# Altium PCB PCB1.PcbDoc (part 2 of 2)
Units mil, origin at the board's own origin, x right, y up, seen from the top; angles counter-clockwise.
Board outline 2130 x 2330 mil, 2 copper layers (Top Layer, Bottom Layer); 110 components, 79 nets, 324 pads, 362 vias.
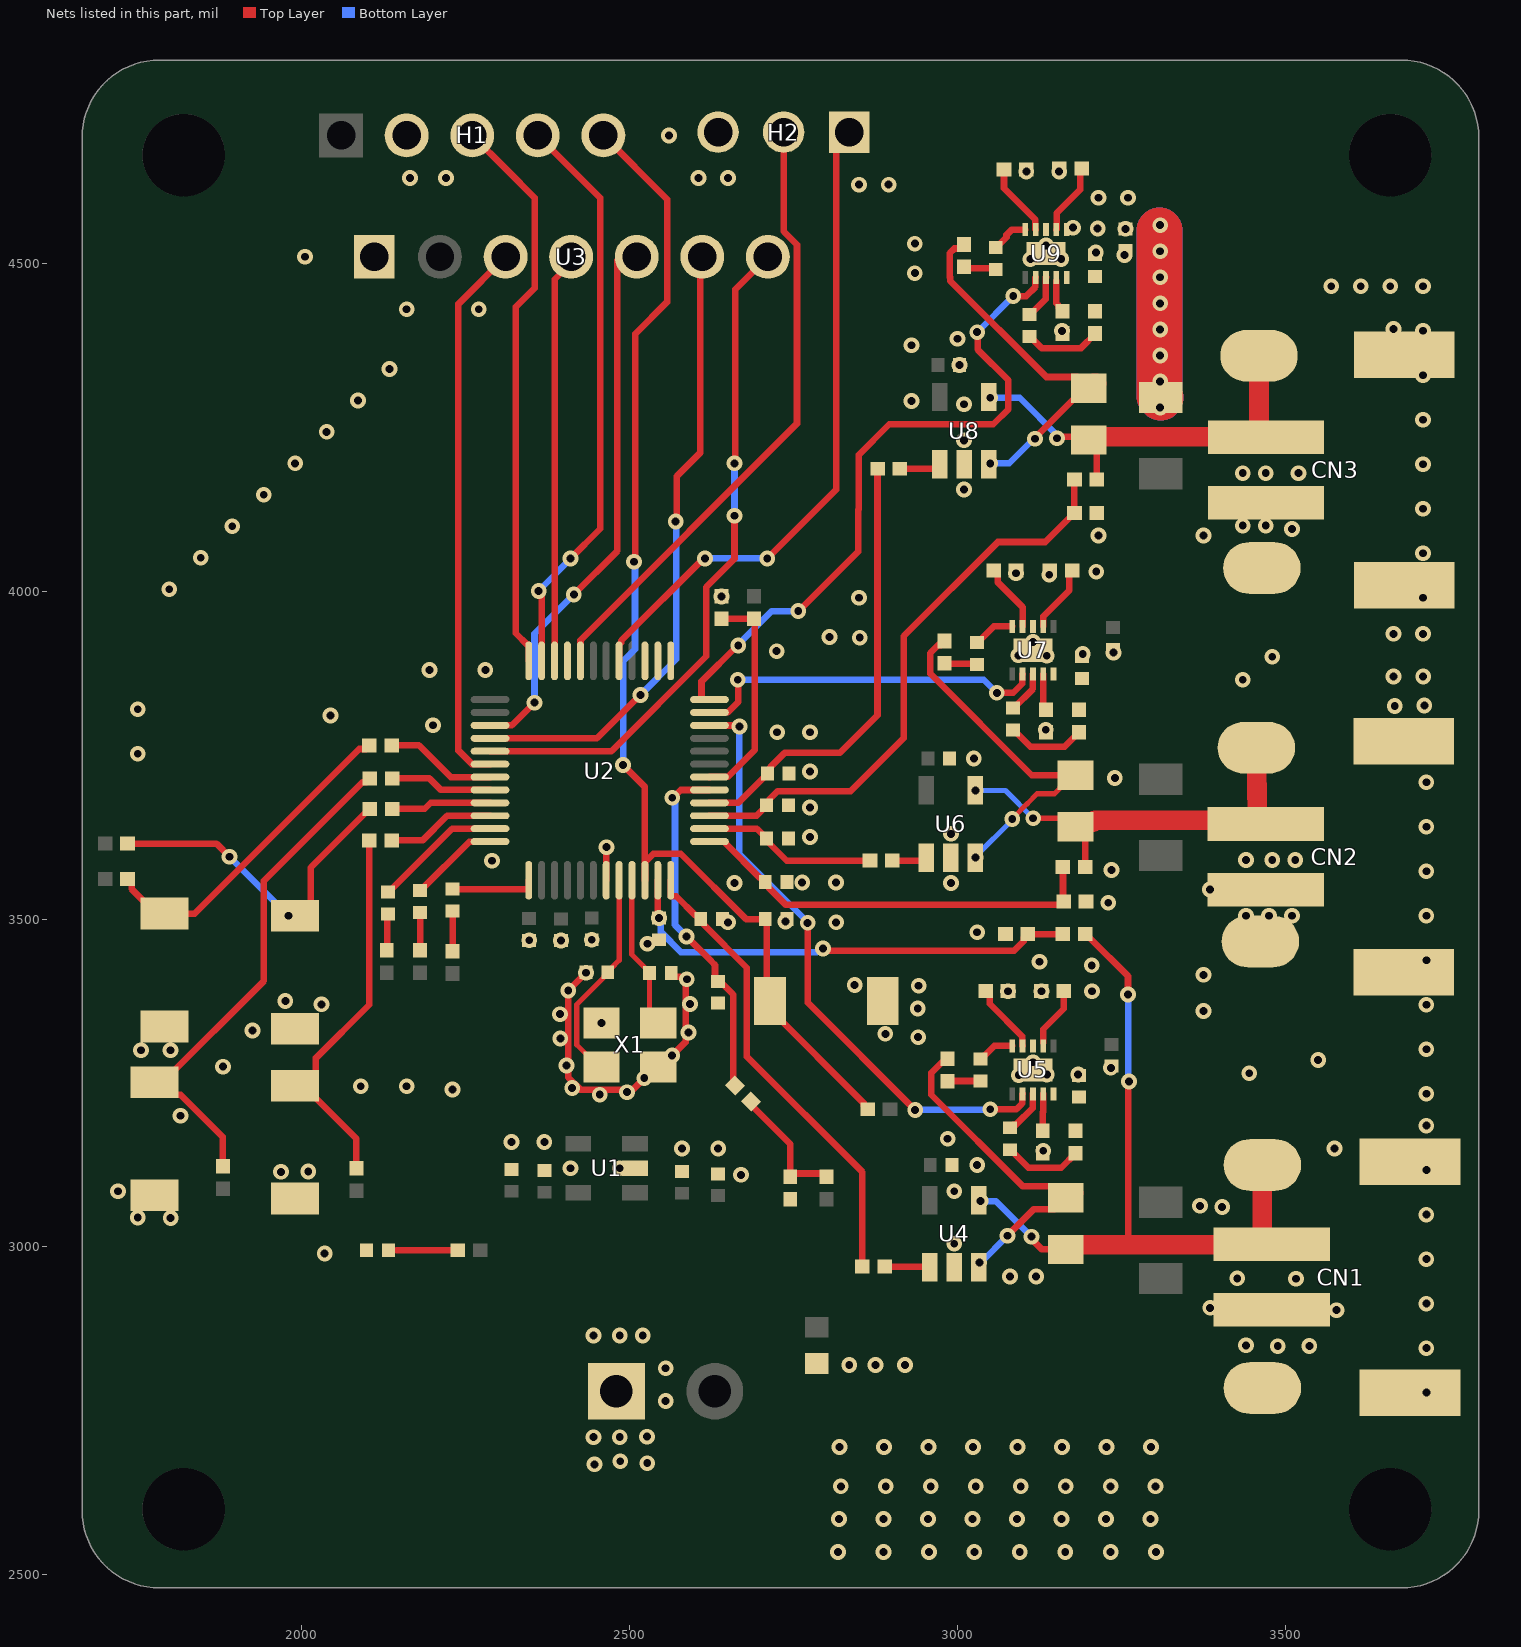
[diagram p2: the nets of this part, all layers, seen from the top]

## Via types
v1: diameter 24, hole 12, Top Layer to Bottom Layer, tented both sides, 362 vias

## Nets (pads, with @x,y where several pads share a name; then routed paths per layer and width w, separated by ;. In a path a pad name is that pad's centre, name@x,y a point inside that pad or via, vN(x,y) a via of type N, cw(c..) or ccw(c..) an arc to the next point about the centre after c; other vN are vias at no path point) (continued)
5V_3: C25.2 R41.1 U9.1 | length 510.5
  Top Layer w70: v1@3308.28,4550.18 3308.28,4513.15 3308.28,4438.95 3308.28,4399.21 3308.28,4359.47 3308.28,4297.34 R41.1@3310,4295.62
  Bottom Layer w70: v1@3308.28,4550.18 3308.28,4513.15 3308.28,4297.34 3310,4295.62
  other v1: 3309.09,4280 3309.09,4319.74 3309.09,4359.47 3309.09,4399.21 3309.09,4438.95 3309.09,4478.69 3309.09,4518.42 3213.76,4553.23 3256.34,4552.54 3176.23,4554.41 3309.09,4558.16 3215,4600 3260,4600
ADC1_IN0: C14.1 R8.2 R13.1 U2.11 | length 723.5
  Top Layer w10: U2.11@2543.08,3559.14 2543.07,3503.47 v1(2545,3501.54) ; v1(2795,3455) 2798.79,3455 2802.03,3451.76 3086.38,3451.76 3101.22,3466.61 3101.22,3471.52 3106.85,3477.15 R8.2@3160.51,3477.15
  Bottom Layer w10: v1(2545,3501.54) 2547.68,3498.86 2547.68,3480.15 2578.39,3449.45 2785.66,3449.45 2791.21,3455 v1(2795,3455)
ADC1_IN1: C15.1 R9.2 U2.12 | length 716.1
  Top Layer w10: U2.12@2562.77,3559.14 2562.77,3535.1 2563.06,3534.81 2571.23,3534.81 2600.41,3505.63 2603.62,3505.63 2608.46,3500.79 C15.1@2608.46,3500 ; C15.1@2608.46,3499.21 2613.3,3494.37 2613.3,3491.29 2678.77,3425.82 2678.77,3290.38 2855,3114.15 R9.2@2855,2970
ADC1_IN2: C21.1 R32.2 R34.1 U2.13 | length 637.8
  Top Layer w10: U2.13@2621.82,3618.19 2645.86,3618.19 2646.15,3617.9 2646.15,3615.56 2699.75,3561.96 2701.98,3561.96 2706.82,3557.12 C21.1@2706.82,3556.33 2711.66,3551.49 2711.66,3548.32 2738.35,3521.63 3156.69,3521.63 R34.1@3161.89,3526.83 ; R34.1@3160.93,3526.83 R32.2@3160.93,3578.69
ADC1_IN3: C22.1 R33.2 U2.14 | length 266.9
  Top Layer w10: U2.14@2621.82,3637.88 2694.09,3637.88 2703.52,3628.45 2704.11,3628.45 2708.95,3623.61 C22.1@2708.95,3623.02 ; C22.1@2708.95,3622.82 2713.79,3617.98 2713.79,3615.03 2739.71,3589.12 R33.2@2866.55,3589.12
ADC1_IN4: C24.1 R40.2 R44.1 U2.15 | length 893.4
  Top Layer w10: U2.15@2621.82,3657.56 2693.67,3657.56 2708.95,3672.84 2708.95,3674.42 2713.79,3679.26 2713.79,3683.1 2725.95,3695.26 2837.37,3695.26 2918.07,3775.96 2918.07,3931.48 3061.59,4075 3133.85,4075 3177.87,4119.02 R44.1@3178.37,4119.02 R40.2@3178.37,4170.41
ADC1_IN5: C27.1 R43.2 U2.16 | length 690.6
  Top Layer w10: U2.16@2621.82,3677.25 2621.94,3677.37 2665.96,3677.37 2710.04,3721.44 2710.04,3723.02 2714.88,3727.86 2714.88,3731.85 2736.42,3753.38 2820.6,3753.38 2878.03,3810.82 R43.2@2878.03,4186.63
ADC1_IN6: C12.2 R4.2 U2.17 | length 542.1
  Top Layer w10: v1(2565,3685) 2565.98,3685 2577.86,3696.88 U2.17@2621.82,3696.93 ; v1(2586.82,3473.54) 2625.2,3435.16 2625.2,3434.84 2630.2,3429.84 2630.2,3409.8 2639.84,3400.16 2642.79,3400.16 2658.03,3384.92 2658.03,3256.79 2660.47,3254.35 2660.47,3246.39 R4.2@2660.83,3246.03
  Bottom Layer w10: v1(2565,3685) 2565,3681.21 2569.25,3676.96 2569.25,3491.11 v1(2586.82,3473.54)
ADC1_IN7: R2.2 R5.2 U2.18 | length 336.7
  Top Layer w10: U2.18@2621.82,3716.62 2621.94,3716.74 2649.54,3716.74 2691.17,3758.37 2691.17,3956.79 R2.2@2690,3957.96 R5.2@2640,3957.96
GND: C1.2 C2.2 C3.1 C4.2 C5.2 C6.2 C7.2 C8.2 C9.2 C10.1 C11.1 C12.1 C13.1 C14.2 C15.2 C16.1 C17.1 C18.1 C19.1 C20.1 C21.2 C22.2 C23.1 C24.2 C25.1 C26.1 C27.2 CN1.2 CN1.3 CN1.4 CN2.2 CN2.3 CN2.4 CN3.2 CN3.3 CN3.4 H1.2 H2.3 LED2.1 P1.1 pad.2@3462,3465.84 pad.2@3464.28,4035.33 pad.2@3465,2785 R5.1 R6.1 R12.2 R13.2 R19.1 R20.1 R31.2 R34.2 R36.1 R37.1 R42.2 R44.2 R46.1 R48.1 SW1.1 SW2.1 SW3.1 SW4.1 SW5.1 U1.2 U2.7 U3.1 U4.2 U5.3 U5.11 U6.2 U7.3 U7.11 U8.2 U9.3 U9.11 X1.2 X1.4 | length 561.3
  Top Layer w10: C5.2@2433.58,3418.96 v1(2433.58,3418.17) v1(2406.49,3391.08) 2406.49,3258.52 2424.93,3240.08 2505.11,3240.08 2539.73,3274.7 X1.4@2543.67,3274.7 2547.6,3274.7 2585.45,3312.54 2585.45,3407.91 2581.66,3407.91 2577.46,3412.1 2568.32,3412.1 2563.48,3416.94 C10.1@2563.48,3417.73 ; U2.7@2464.34,3559.14 2464.34,3609.34 v1(2464.67,3609.67) v1@2465,3610
  other v1: 2817.86,2535 2887.14,2535 2956.43,2535 3025.71,2535 3095,2535 3164.29,2535 3233.57,2535 3302.86,2535 2819.29,2585 2887.14,2585 2955,2585 3022.86,2585 3090.71,2585 3158.57,2585 3226.43,2585 3294.29,2585 2822.14,2635 2890.71,2635 2959.29,2635 3027.86,2635 3096.43,2635 3165,2635 3233.57,2635 3302.14,2635 2446.52,2668.55 2526.89,2670.37 2485.79,2673.28 2820,2695 2887.86,2695 2955.71,2695 3023.57,2695 3091.43,2695 3159.29,2695 3227.14,2695 3295,2695 2445,2710 2485,2710 2526.53,2710.74 2555,2765 3715,2777.86 2555,2815 2835,2820 2875,2820 2920,2820 3715,2845.71 3488.43,2848.78 3536.61,2849.12 3440,2850 2445,2865 2485,2865 2520,2865 3578.06,2903.69 3385.32,2907.12 3715,2913.57 3426.65,2952.17 3516.09,2951.59 3080,2955 3120,2955 3715,2981.43 2035,2990 2995,3005 1800.18,3044.25 1750,3045 3715,3049.29 3403.64,3061.12 3369.68,3062.66 1720,3085 2995,3085 2670,3110 1968.49,3114.59 2010,3115 3715,3117.14 2410,3120 2485,3120 3030,3125 3130.83,3146.63 2580,3150 2635,3150 3575,3150 2320,3160 2370,3160 2985,3165 3715,3185 1815,3200 2454.56,3232.32 3715,3233.57 2496.02,3236.09 2230,3240 2412.37,3242.45 2090,3245 2160,3245 2522.42,3257.39 3093.47,3261.97 3136.31,3262.86 3183.97,3262.95 3445,3265 3233.86,3273.17 1880,3275 2403.68,3276.65 3115.19,3281.75 3550,3285 2564.91,3292.01 1755,3300 1800,3300 3715,3301.43 2394.45,3318.02 2940,3320 2890,3325 2589.68,3327.19 1925,3330 2457.05,3341.63 2393.87,3355 3375,3360 2939.42,3363.65 3715,3369.29 2030,3370 2592.05,3370.63 1975,3375 3077.04,3390 3127.96,3390 3205,3390 2940.82,3398.4 2843.24,3399.46 2587.3,3408.24 3375,3415 3204.71,3429.49 3125,3435 3715,3437.14 2527.37,3462.32 2395.45,3467.22 2346.91,3467.65 2442.28,3468.5 3030,3480 2650,3495 2815,3495 2737.58,3496.3 3440,3505 3475,3505 3510,3505 3715,3505 3230,3525 3385,3545 2660,3555 2990,3555 2763.12,3555.81 2814.63,3555.94 3715,3572.86 3235,3575 2290.28,3588.86 3440,3590 3480,3590 3515,3590 2775,3625 2990,3630 3715,3640.71 2775,3670 3715,3708.57 3240,3715 2775,3725 3025,3745 1750,3752.14 2725,3785 2775,3785 3134.63,3788.73 2200.07,3795.54 2043.73,3810.45 1750,3820 3666.89,3824.99 3711.99,3825.59 3435,3865 3665,3870 3710.16,3870.08 2195,3880 2280,3880 3480,3900 3093.18,3902.2 3136.07,3901.63 3191.07,3904.31 3237.99,3906.26 2724.25,3908.61 3115.12,3922.45 2851.01,3929.19 2805,3930 3665,3935 3710,3935 2850,3990 3710,3990 2640,3992.04 1798.07,4003.07 3140,4025 3089.06,4027.34 3211.66,4029.77 1846.05,4051.05 3710,4057.86 3215,4085 3375,4085 3510,4095 1894.04,4099.04 3435,4100 3470,4100 3710,4125.71 1942.02,4147.02 3010,4155 3435,4180 3470,4180 3520,4180 3710,4193.57 1990,4195 3010,4230 2037.98,4242.98 3710,4261.43 3010,4285 2930,4290 2085.96,4290.96 3710,4329.29 2133.95,4338.95 3003.08,4345 2930,4375 3000,4385 3159.41,4397.06 3710,4397.14 3665,4400 2160,4430 2270,4430 3570,4465 3615,4465 3660,4465 3710,4465 2935,4485 3111.11,4506.4 3158.15,4506.73 2005,4510 3254.86,4512.55 3210.96,4516.66 3135.05,4527.14 2935,4530 2850,4620 2895,4620 2165,4630 2220,4630 2605,4630 2650,4630 3105,4640 3155,4640 2560,4695
NetC5_1: C5.1 U2.8 X1.3 | length 329.3
  Top Layer w8: X1.3@2457.05,3274.7 2453.11,3274.7 2419.49,3308.32 2419.49,3369.94 2460.81,3411.27 2460.81,3413.11 C5.1@2466.66,3418.96 2466.66,3419.74 2472.5,3425.59 2484.31,3437.39 2484.31,3558.86 U2.8@2484.03,3559.14
NetC10_2: C10.2 U2.9 X1.1 | length 234.4
  Top Layer w8: U2.9@2503.71,3559.14 2503.71,3546.1 2503.25,3545.65 2503.25,3446.08 2524.56,3424.77 2524.56,3423.57 C10.2@2530.4,3417.73 ; C10.2@2530.4,3417.73 2530.39,3354.9 X1.1@2543.67,3341.63
NetLED1_1: LED1.1 U5.5 | length 56.7
  Top Layer w10: LED1.1@3035,3286.73 3039.84,3291.57 3041.02,3291.57 3055.97,3306.52 U5.5@3083.5,3306.52
NetLED1_2: LED1.2 R7.1 | length 50.1
  Top Layer w10: R7.1@2985,3252.96 2985.16,3253.12 3034.85,3253.12 LED1.2@3035,3253.27
NetLED2_2: LED2.2 R11.1 | length 80.3
  Top Layer w10: 2145,2995 2225.34,2995
NetLED3_1: LED3.1 U5.8 | length 68.8
  Top Layer w10: LED3.1@3080,3181.73 3084.84,3186.57 3089.28,3186.57 3114.66,3211.95 3114.66,3233.14 U5.8@3115,3233.48
NetLED3_2: LED3.2 R16.1 | length 120.8
  Top Layer w10: LED3.2@3080,3148.27 3080.79,3148.27 3108.23,3120.83 3158.37,3120.83 3180,3142.46 R16.1@3180,3142.96
NetLED4_2: LED4.2 R18.1 | length 61.1
  Top Layer w10: R18.1@2230,3451.07 LED4.2@2230,3512.18
NetLED5_2: LED5.2 R23.1 | length 56.1
  Top Layer w10: R23.1@2129.65,3452.27 2130.67,3453.3 2130.67,3506.52 LED5.2@2131.7,3507.55
NetLED6_2: LED6.2 R25.1 | length 57.8
  Top Layer w10: R25.1@2180.51,3452.27 LED6.2@2180.51,3510.1
NetLED7_1: LED7.1 U7.5 | length 63.8
  Top Layer w10: LED7.1@3030,3921.73 3030.79,3921.73 3055.58,3946.52 U7.5@3083.5,3946.52
NetLED7_2: LED7.2 R28.1 | length 50.7
  Top Layer w10: R28.1@2980,3890 2980.86,3889.14 3029.13,3889.14 LED7.2@3030,3888.27
NetLED8_1: LED8.1 U7.8 | length 64.6
  Top Layer w10: LED8.1@3085,3821.73 3085.79,3821.73 3115,3850.94 U7.8@3115,3873.48
NetLED8_2: LED8.2 R35.1 | length 120
  Top Layer w10: LED8.2@3085,3788.27 3085.79,3788.27 3111.19,3762.86 3163.37,3762.86 3185,3784.49 R35.1@3185,3785
NetLED9_1: LED9.1 U9.5 | length 58.4
  Top Layer w10: LED9.1@3058.4,4524.2 3059.19,4524.2 3074.77,4539.79 3074.77,4543.24 3083.05,4551.52 U9.5@3103.5,4551.52
NetLED9_2: LED9.2 R39.1 | length 52.5
  Top Layer w10: R39.1@3010,4494.62 3008.75,4493.37 3009.44,4492.68 3056.46,4492.68 LED9.2@3058.4,4490.74
NetLED10_1: LED10.1 U9.8 | length 67.6
  Top Layer w10: LED10.1@3110,4421.73 3110.79,4421.73 3134.63,4445.57 3134.63,4452.92 ; 3134.66,4452.95 3134.66,4478.14 U9.8@3135,4478.48
NetLED10_2: LED10.2 R45.1 | length 116.7
  Top Layer w10: LED10.2@3110,4388.27 3110.79,4388.27 3128.23,4370.82 3188.37,4370.82 3210,4392.45 R45.1@3210,4392.96
NetR3_2: R3.2 R4.1 R6.2 | length 194
  Top Layer w10: R4.1@2684.93,3221.93 2684.93,3216.96 2745.17,3156.72 R6.2@2745.17,3112.04 ; R6.2@2745,3107.04 2750,3112.04 2795,3112.04 R3.2@2800,3107.04
NetR9_1: R9.1 U4.1 | length 69
  Top Layer w10: R9.1@2889.08,2970 2956.41,2970 U4.1@2957.6,2968.81
NetR12_1: R12.1 U5.9 | length 56.8
  Top Layer w10: R12.1@3130,3177.04 3130,3205.65 3130.75,3206.4 U5.9@3130.75,3233.48
NetR14_1: R14.1 R15.2 SW2.2 | length 504.7
  Top Layer w10: R15.2@1734.37,3615.14 1869.86,3615.14 v1(1890,3595) ; SW2.2@1990,3504.98 1994.69,3504.98 2013.9,3524.19 2013.9,3578.57 2103.51,3668.18 R14.1@2104.02,3668.18
  Bottom Layer w10: v1(1890,3595) v1(1980,3505)
NetR19_2: R19.2 U5.4 | length 107.1
  Top Layer w10: R19.2@3042.96,3390 3043.47,3390 3049.09,3384.37 3049.09,3370.83 3098.91,3321.02 3098.91,3306.86 U5.4@3099.25,3306.52
NetR20_2: R20.2 U5.2 | length 91.5
  Top Layer w10: U5.2@3130.7,3311.46 3130.7,3332.05 3162.04,3363.39 R20.2@3162.04,3390
NetR21_1: R21.1 R22.2 SW3.2 | length 781.3
  Top Layer w10: R22.2@1879.63,3122.96 1879.63,3167.89 1815.66,3231.86 1800.78,3231.86 1781.57,3251.08 1787.77,3251.08 1942.39,3405.69 1942.39,3558.32 2092.93,3708.87 2098.39,3708.87 R21.1@2104.02,3714.5
NetR24_1: R24.1 R26.2 SW4.2 | length 502.1
  Top Layer w10: R26.2@1734.37,3561 1734.87,3561 1740.5,3555.37 1740.5,3546.07 1778.17,3508.41 SW4.2@1790.57,3508.41 1836.92,3508.41 2087.88,3759.37 2097.33,3759.37 R24.1@2102.96,3765
NetR27_1: R27.1 R29.2 SW5.2 | length 575.4
  Top Layer w10: R29.2@2083.42,3119.81 2083.42,3165 2002.4,3246.02 2021.61,3265.23 2021.61,3288.17 2102.96,3369.51 R27.1@2102.96,3620
NetR31_1: R31.1 U7.9 | length 56.2
  Top Layer w10: U7.9@3130.75,3873.48 3131.09,3873.14 3131.09,3822.99 R31.1@3135,3819.08
NetR33_1: R33.1 U6.1 | length 53.9
  Top Layer w10: R33.1@2900.63,3589.12 2947.9,3589.12 U6.1@2952.6,3593.81
NetR36_2: R36.2 U7.4 | length 103.2
  Top Layer w10: R36.2@3055.19,4031.28 3055.47,4031.28 3061.1,4025.65 3061.1,4013.9 3099.25,3975.75 U7.4@3099.25,3946.52
NetR37_2: R37.2 U7.2 | length 103
  Top Layer w10: U7.2@3130.75,3946.52 3131.09,3946.86 3131.09,3961.88 3170.73,4001.52 3170.73,4027.13 R37.2@3174.88,4031.28
NetR42_1: R42.1 U9.9 | length 50.4
  Top Layer w10: U9.9@3150.6,4473.54 3150.6,4439.27 3154.37,4435.5 3154.37,4432.67 R42.1@3160,4427.04
NetR43_1: R43.1 U8.1 | length 63.4
  Top Layer w10: R43.1@2912.24,4186.76 2965.79,4186.76 2972.6,4193.57 U8.1@2972.6,4193.81
NetR46_2: R46.2 U9.4 | length 111.8
  Top Layer w10: R46.2@3070.92,4643.23 3070.92,4614.37 3118.91,4566.38 3118.91,4551.86 U9.4@3119.25,4551.52
NetR48_2: R48.2 U9.2 | length 109
  Top Layer w10: U9.2@3150.75,4551.52 3151.09,4551.86 3151.09,4576.38 3187.1,4612.39 3187.1,4642.02 R48.2@3189.54,4644.45
NRST: C11.2 H1.5 R1.1 SW1.2 U2.10 | length 1829.4
  Top Layer w10: H1.5@2460,4695 2557.23,4597.77 2557.23,4440.82 2508.65,4392.24 v1@2508.65,4046.05 ; v1(2490,3735) 2523.4,3701.6 U2.10@2523.4,3559.14 2523.52,3559.26 2523.52,3586.87 2536.32,3599.67 2577.9,3599.67 2677.57,3500 C11.2@2706.82,3500 2708.9,3497.92 2708.9,3380.08 SW1.2@2713.98,3375 2713.98,3362.6 2856.82,3219.75 2856.82,3215.63 2862.45,3210 R1.1@2862.96,3210
  Bottom Layer w10: v1(2490,3735) 2490,3893.11 2508.27,3911.37 2508.27,4043.91 v1@2507.35,4044.82
  other v1: 2506.73,4044.82
PB4: R24.2 U2.43 | length 170.2
  Top Layer w10: R24.2@2137.04,3765 2178.79,3765 2227.17,3716.62 U2.43@2287.18,3716.62
PB5: R21.2 U2.44 | length 156.4
  Top Layer w10: R21.2@2138.1,3714.5 2194.67,3714.5 2212.24,3696.93 U2.44@2287.18,3696.93
PB6: R14.2 U2.45 | length 152.8
  Top Layer w10: R14.2@2138.1,3668.18 2187.77,3668.18 2196.84,3677.25 U2.45@2287.18,3677.25
PB7: R27.2 U2.46 | length 165.7
  Top Layer w10: R27.2@2137.04,3620 2184.2,3620 2221.76,3657.56 U2.46@2287.18,3657.56
PB8: LED5.1 U2.47 | length 195.6
  Top Layer w10: LED5.1@2131.7,3541.01 2132.49,3541.01 2229.35,3637.88 U2.47@2287.18,3637.88
PB9: LED6.1 U2.48 | length 137.6
  Top Layer w10: LED6.1@2180.51,3543.56 2181.3,3543.56 2255.8,3618.07 2287.06,3618.07 U2.48@2287.18,3618.19
PB10: U2.22 U5.7 | length 914
  Top Layer w10: U2.22@2621.82,3795.36 2621.94,3795.24 2665.77,3795.24 v1(2667.48,3793.54) ; v1@2771.99,3493.74 2771.99,3372.47 v1(2935.42,3209.04) ; v1(3050,3210) 3089.93,3210 3098.91,3218.98 3098.91,3233.14 U5.7@3099.25,3233.48
  Bottom Layer w10: v1@2667.17,3785.83 2667.17,3599.44 v1@2770.78,3495.82 ; v1(2935.42,3209.04) 2935.9,3209.52 3049.52,3209.52 v1(3050,3210)
  other v1: 2771.49,3494.22
PB11: U2.23 U7.7 | length 547.4
  Top Layer w10: U2.23@2621.82,3815.04 2621.94,3815.16 2649.53,3815.16 2665.96,3831.59 2665.96,3864.04 v1(2665,3865) ; v1(3060,3845) 3084.93,3845 3098.91,3858.98 3098.91,3873.14 U7.7@3099.25,3873.48
  Bottom Layer w10: v1(2665,3865) 3040,3865 v1(3060,3845)
PB12: U2.24 U9.7 | length 1034.4
  Top Layer w10: U2.24@2621.82,3834.73 2609.94,3834.73 2609.65,3835.02 2609.65,3862.39 v1@2664.76,3917.5 ; v1@2757.93,3969.72 2848.63,4060.42 2848.63,4124.31 2849.32,4125 2849.32,4207.68 2896.1,4254.45 3054.69,4254.45 3077.75,4277.52 3077.75,4321.61 3030.73,4368.63 3030.73,4394.27 v1(3030,4395) ; v1(3085,4450) 3104.93,4450 3118.91,4463.98 3118.91,4478.14 U9.7@3119.25,4478.48
  Bottom Layer w10: v1@2664.51,3917.5 2716.72,3969.72 v1(2757.12,3969.72) ; v1(3030,4395) v1(3085,4450)
  other v1: 2665.79,3917.25
PB13: U2.25
PB14: U2.26
PB15: U2.27
PC13: LED4.1 U2.1 | length 129.6
  Top Layer w10: LED4.1@2230,3545.65 2345.94,3545.65 2346.23,3545.94 U2.1@2346.23,3559.14
PD1: U2.39 U3.5 | length 808.9
  Top Layer w10: U2.39@2287.18,3795.36 2287.3,3795.48 2320.48,3795.48 v1(2355,3830) ; v1(2415,3995) 2481.4,4061.4 U3.5@2481.4,4504.38
  Bottom Layer w10: v1(2355,3830) 2355,3935 v1(2415,3995)
PD2: U2.40 U3.6 | length 966.2
  Top Layer w10: U2.40@2287.18,3775.67 2450.16,3775.67 v1@2517.26,3842.77 ; v1(2570.19,4106.37) 2572.12,4108.3 2572.12,4175.61 2608.03,4211.52 2608.03,4507.13 U3.6@2610.85,4509.95
  Bottom Layer w10: v1(2516.48,3841.73) 2571.11,3896.36 2571.11,4106.41 v1@2570.67,4106.85
PD3: U2.41 U3.7 | length 1037.9
  Top Layer w10: U2.41@2287.18,3755.99 2472.26,3755.99 2617,3900.73 2617,4006.36 2660,4049.36 v1(2660,4115) ; v1(2660,4195) 2660.99,4195.99 2660.99,4460.1 U3.7@2710.85,4509.95
  Bottom Layer w10: v1(2660,4115) v1(2660,4195)
SPI1_MISO: U2.33
SPI1_MOSI: U2.34 U3.4 | length 626.3
  Top Layer w10: U2.34@2385.89,3894.13 2385.72,3894.3 2385.72,3918.28 2385.94,3918.51 2385.94,4475.63 2410.85,4500.54 U3.4@2410.85,4509.95
SPI1_SCK: U2.42 U3.3 | length 839.6
  Top Layer w10: U2.42@2287.18,3736.3 2287.06,3736.42 2259.46,3736.42 2238.9,3756.98 2238.9,4438 U3.3@2310.85,4509.95
SWCLK: H1.3 U2.36 | length 861.9
  Top Layer w10: H1.3@2260,4695 2312.83,4642.17 2355.31,4599.69 2355.31,4462.41 2326.43,4433.53 2326.43,3935.79 2344.11,3918.11 2345.94,3918.11 2346.23,3917.82 U2.36@2346.23,3893.78
SWDIO: H1.4 U2.35 | length 881.5
  Top Layer w10: H1.4@2360,4695 2455.31,4599.69 2455.31,4095.31 v1(2410,4050) ; v1(2361.35,4000.16) 2361.35,3996.37 2365.92,3991.81 U2.35@2365.92,3893.78
  Bottom Layer w10: v1(2361.35,4000.16) 2361.35,4000.76 2410,4049.4 v1(2410,4050)
USART1_RX: H2.2 U2.32 | length 951.5
  Top Layer w10: U2.32@2424.97,3893.78 2425.09,3893.9 2425.09,3925.3 2755.32,4255.53 2755.32,4528.37 2735,4548.68 H2.2@2735,4700
USART1_TX: H2.1 U2.29 | length 1008.6
  Top Layer w10: U2.29@2484.03,3893.78 2484.03,3918.16 2487.39,3921.53 2487.39,3924.75 2612.64,4050 v1(2615,4050) ; v1(2710,4050) 2814.86,4154.86 2814.86,4679.86 H2.1@2835,4700
  Bottom Layer w10: v1(2615,4050) v1(2710,4050)
VBAT1: CN1.1 pad.2@3465,3125 R8.1 R17.2 U4.4 | length 1098
  Top Layer w10: v1(3112.74,3015.68) 3112.74,3012.26 3128.74,2996.26 R17.2@3165,2996.26 ; R8.1@3194.59,3477.15 3200.22,3471.52 3201.52,3471.52 3260,3413.04 v1(3260,3385) ; 3259.84,3003.17 3260.53,3003.86 v1@3260.53,3251.95
  Top Layer w30: R17.2@3165,2996.26 3171.92,3003.17 3259.84,3003.17 CN1.1@3467.04,3003.17 ; pad.2@3465,3125 3465,3014.58 3475.59,3003.99 CN1.1@3479.37,3003.99
  Bottom Layer w10: v1(3035,3070) 3058.42,3070 v1(3112.74,3015.68) ; v1@3260.23,3384.77 3260.23,3253.73 v1@3261.12,3252.84
  other v1: 3261.72,3252.25
VBAT1_H: C17.2 R7.2 R16.2 R17.1 U4.3 U5.10 | length 525.1
  Top Layer w10: R7.2@2985,3287.04 2985,3286.54 2979.37,3280.91 2975.62,3280.91 2960,3265.28 2960,3232.24 3099.95,3092.29 3147.71,3092.29 R17.1@3165,3075 3147.7,3057.7 3116.56,3057.7 v1@3076.39,3017.53
  Top Layer w30: R17.1@3165,3075 3172.29,3082.29 R17.1@3177.11,3082.29
  Bottom Layer w10: v1(3033.32,2976.07) 3035.35,2976.07 v1(3076.39,3017.1)
VBAT2: CN2.1 pad.2@3455.86,3761.23 R32.1 R38.2 U6.4 | length 686.8
  Top Layer w8: v1(3115.39,3653.84) 3115.59,3653.63 3162.18,3653.63 3175.19,3640.63 R38.2@3180,3640.63
  Top Layer w10: R38.2@3180,3640.63 3194.59,3626.04 R32.1@3194.59,3579.11 ; 3267.86,3640.78 3291.77,3640.78
  Top Layer w30: R38.2@3180,3640.63 3187.3,3647.92 3206.68,3647.92 3209.68,3650.93 3464.07,3650.93 CN2.1@3470,3645 3467.59,3645 3457,3655.59 pad.2@3455.86,3761.23
  Bottom Layer w8: v1(3027.4,3696.19) 3073.04,3696.19 v1(3115.39,3653.84)
VBAT2_H: C20.2 R28.2 R35.2 R38.1 U6.3 U7.10 | length 553.4
  Top Layer w8: v1@3083.46,3653.03 3106.27,3675.84 ; 3106.31,3675.84 3121.52,3691.06 3147.69,3691.06 3156.89,3700.26 3156.89,3701.08 3175.19,3719.37 R38.1@3180,3719.37
  Top Layer w10: R28.2@2980,3924.08 2980,3923.57 2974.37,3917.95 2970.62,3917.95 2958.37,3905.69 2958.37,3874.31 3113.31,3719.37 R38.1@3180,3719.37
  Bottom Layer w8: v1(3027.4,3593.81) 3027.4,3595.23 3083.46,3651.29 v1(3083.46,3652.7)
VBAT3: CN3.1 pad.2@3459.81,4359.02 R40.1 R47.2 U8.4 | length 641.1
  Top Layer w10: v1(3151.73,4233.19) 3153.85,4235.32 3184.69,4235.32 3190,4240.63 R47.2@3200,4230.63 3212.45,4218.18 R40.1@3212.45,4170.41
  Top Layer w30: R47.2@3200,4230.63 3204.95,4235.58 CN3.1@3457.74,4235.58 ; pad.2@3459.81,4359.02 3459.81,4245.44 3470.4,4234.85 CN3.1@3470.63,4234.85
  Bottom Layer w10: v1(3050,4295) 3094.86,4295 3154.53,4235.33 v1@3154.53,4232.96
VBAT3_H: C26.2 R39.2 R45.2 R47.1 U8.3 U9.10 | length 562.4
  Top Layer w10: R39.2@3010,4528.7 3010,4528.2 3004.37,4522.57 2995.25,4522.57 2988.37,4515.69 2988.37,4478.93 2988.66,4478.65 2988.66,4473.58 3135.58,4326.66 3182.71,4326.66 3196.74,4312.63 R47.1@3200,4309.37 3182.7,4292.08 3176.19,4292.08 3118.27,4234.16 v1(3118.27,4232.51)
  Top Layer w30: R47.1@3200,4309.37 3207.29,4316.66 R47.1@3212.11,4316.66
  Bottom Layer w10: v1(3050,4195) 3078.8,4195 3116.32,4232.51 v1(3118.27,4232.51)
pads on no net: *1.1 *2.1 *3.1 *4.1 U1.4 U2.2 U2.3 U2.19 U2.20 U2.21 U2.28 U2.30 U2.31 U2.37 U2.38 U5.6 U7.6 U9.6

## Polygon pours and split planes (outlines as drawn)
VBAT1_H on Top Layer "NONET_L-01_P-001" (hatched Horizontal grid 4 track 5, remove dead copper, pour order 15): 3138.74,3244.96 3138.74,3185.34 3165.96,3158.12 3196.29,3158.12 3196.29,3129.52 3176.64,3109.88 3128.74,3109.88 3128.74,3077.49 3127.37,3076.11 3130.81,3072.66 3244.53,3072.66 3244.53,3245.3 3243.15,3246.68
VBAT3_H on Top Layer "NONET_L-01_P-001" (hatched Horizontal grid 4 track 5, remove dead copper, pour order 14): 3157.18,4490.63 3157.18,4448.16 3161.56,4443.78 3176.55,4443.78 3176.55,4423.17 3190.92,4408.8 3224.65,4408.8 3224.65,4372.88 3210.59,4358.83 3164.99,4358.83 3164.99,4311.98 3167.8,4309.17 3168.12,4309.48 3262.44,4309.48 3262.44,4487.44 3265,4490
VBAT2_H on Top Layer "NONET_L-01_P-001" (hatched Horizontal grid 4 track 5, remove dead copper, pour order 13): 3137.26,3884.49 3138.9,3882.85 3138.9,3838.49 3143.33,3838.49 3154.31,3827.52 3154.07,3827.28 3154.07,3800.2 3198.2,3800.2 3200.07,3798.33 3200.07,3767.04 3182.32,3767.04 3164.35,3749.06 3144.27,3749.06 3144.27,3725.72 3144.5,3725.48 3144.73,3725.72 3223.89,3725.72 3262.65,3764.47 3262.65,3884.96
GND on Top Layer "NONET_L-01_P-001" (solid, remove dead copper, pour order 16): 1665,2598.11 1665,4691.89 cw(c1783.11,4691.89) 1783.11,4810 3676.89,4810 cw(c3676.89,4691.89) 3795,4691.89 3795,2598.11 cw(c3676.89,2598.11) 3676.89,2480 1783.11,2480 cw(c1783.11,2598.11)
5V_1 on Top Layer "NONET_L-01_P-001" (hatched Horizontal grid 4 track 5, remove dead copper, pour order 9): 3170,3355 3139.76,3324.76 3139.76,3296.15 3338.85,3296.15 3340,3295 3340,3355
5V_2 on Top Layer "NONET_L-01_P-001" (hatched Horizontal grid 4 track 5, remove dead copper, pour order 8): 3138.03,3939.64 3139.13,3940.74 3139.13,3974.18 3143.65,3974.18 3179.47,4010 3330,4010 3330,3945.48 3319.31,3934.78 3142.43,3934.78
5V_3 on Top Layer "NONET_L-01_P-001" (hatched Horizontal grid 4 track 5, remove dead copper, pour order 7): 3160,4540 3335,4540 3335,4610 3193.61,4610 3158.39,4574.77 3158.39,4564.37
3V3 on Top Layer "NONET_L-01_P-001" (hatched Horizontal grid 4 track 5, remove dead copper, pour order 0): 2395,3595 2395,3525 2330,3525 2320,3515 2320,3480 2455,3480 2455,3485 2455,3490 2455,3595
5V_1 on Bottom Layer "NONET_L-01_P-001" (hatched Horizontal grid 4 track 5, remove dead copper, pour order 3): 3170,3355 3139.76,3324.76 3139.76,3296.15 3248.78,3296.15 3248.78,3355
5V_2 on Bottom Layer "NONET_L-01_P-001" (hatched Horizontal grid 4 track 5, remove dead copper, pour order 5): 3138.03,3939.64 3139.13,3940.74 3139.13,3974.18 3143.65,3974.18 3179.47,4010 3330,4010 3330,3945.48 3319.31,3934.78 3142.43,3934.78
5V_3 on Bottom Layer "NONET_L-01_P-001" (hatched Horizontal grid 4 track 5, remove dead copper, pour order 2): 3165.99,4540 3335,4540 3335,4610 3200,4610 3163.76,4573.76
GND on Bottom Layer "NONET_L-01_P-001" (solid, remove dead copper, pour order 6): 1665,2598.11 1665,4691.89 cw(c1783.11,4691.89) 1783.11,4810 3676.89,4810 cw(c3676.89,4691.89) 3795,4691.89 3795,2598.11 cw(c3676.89,2598.11) 3676.89,2480 1783.11,2480 cw(c1783.11,2598.11)

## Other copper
Top Layer:
  pour cut-out: 2474.11,3441.62 2470.73,3445 2395,3445 2395,3225 2595,3225 2595,3430 2585,3440

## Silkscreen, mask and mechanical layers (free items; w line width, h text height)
Top Overlay:
  lines w10: 2050,4330 2080,4300 ; 2080,4380 2080,4300 ; 2110,4330 2080,4300
  text "GND" at 2581.97,4762.64 h30
  text "RX" at 2688.41,4762.64 h30
  text "TX" at 2797.28,4762.64 h30
  text "3V3" at 2015,4757.42 h30
  text "GND" at 2114.05,4757.42 h30
  text "CLK" at 2204.05,4757.42 h30
  text "DIO" at 2299.76,4757.42 h30
  text "RST" at 2404.05,4757.42 h30
  text "OLED" at 2025,4395 h30
  text "+" at 3458.55,4280.17 h30
  text "-" at 3445,3965 h30
  text "+" at 3440,3815 h30
  text "-" at 3445,3395 h30
  text "RST" at 2743.55,3265.17 h30
  text "+" at 3447.26,3180.02 h30
  text "GND" at 2453.87,2869.58 h30
  text "5V" at 2623.87,2869.58 h30
  text "Triple 1S Battery Charger / Ver 1.0 / 2026/10/12" at 1755,2760 h30
  text "-" at 3440.82,2714.9 h30
Top Solder:
  lines w30: 2745.36,2582.04 2893.32,2730 3060,2730 3060,2725 2920,2585 3110,2585 3255,2730 ; 2835,2580 2940,2685 2940,2690 ; 3060,2620 3165,2725 ; 3185,2585 3295,2695 ; 3260,2730 3255,2730 ; 3270,2580 3415,2725 3415,2730 3255,2730 ; 3295,2695 3295,2695
  lines w70: 2630,2780 2745,2895 3275,2895 3305,2925 ; 3308.28,4550.18 3308.28,4513.15 3308.28,4297.34 3310,4295.62 ; 3310,3068.22 3315.63,3073.85 3315.63,3259.73 3315.63,3270 3315.63,3285.68 3315.63,3302.05 3315.63,3304.54 3315.63,3591.15 3310,3596.78 ; 3310,3713.22 3305.56,3717.66 3305.56,3902.61 3305.56,3949.96 3305.56,3981.88 3305.56,4174.75 3310,4179.18
Mechanical 1:
  the board outline again, w10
